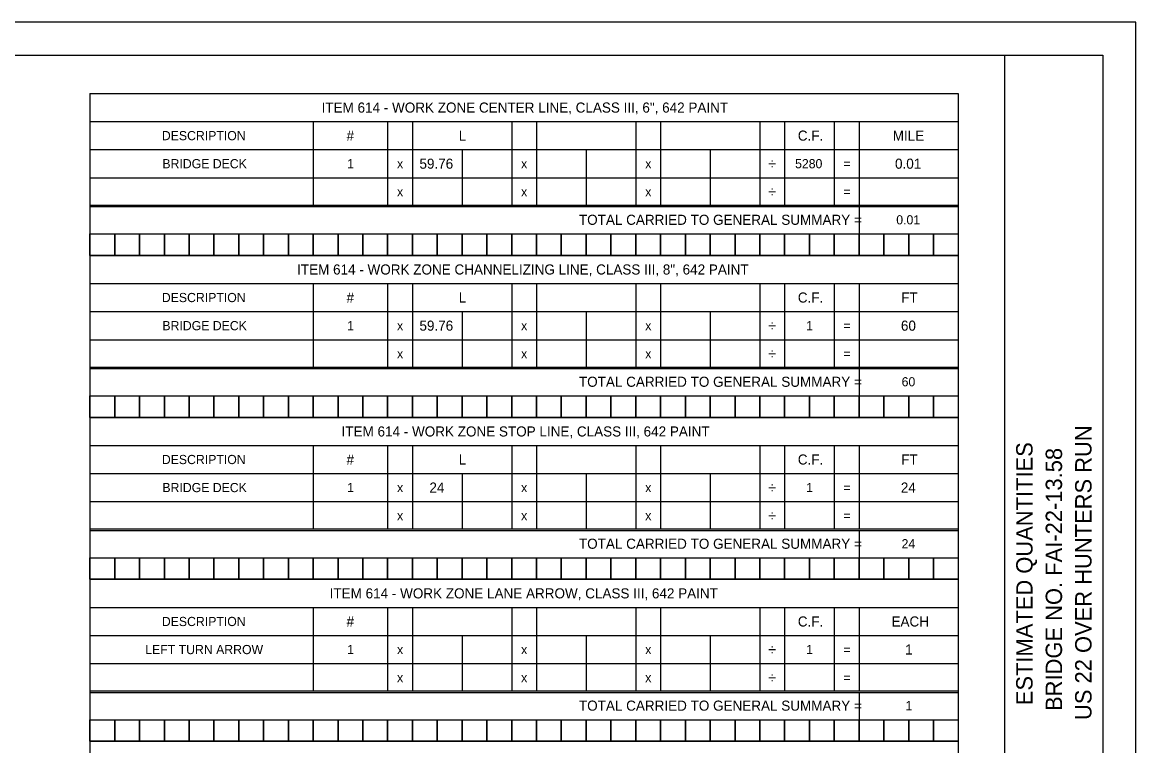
# Model space of a CAD drawing. Extents: x 0 to 34, y 0 to 22.
# Drawn here: x 17 to 34, y 10.96 to 22 of the extents above; entities that cross this region are included whole.
import ezdxf

# ---------------------------------------------------------------- set-up
doc = ezdxf.new("R2010")
doc.units = 0
for name, color, linetype in [('SH_Border', 7, 'Continuous'), ('SH_Cut_Line', 7, 'Continuous'), ('SH_Data', 7, 'Continuous'), ('SH_Text', 7, 'Continuous')]:
    doc.layers.add(name, color=color, linetype=linetype)

msp = doc.modelspace()

# ---------------------------------------------------------------- linework, layer by layer
at = {"layer": 'SH_Border'}
msp.add_line((32, 0.5), (32, 21.5), dxfattribs=at)
msp.add_lwpolyline([(1.5, 21.5), (33.5, 21.5), (33.5, 0.5), (1.5, 0.5)], close=True, dxfattribs=at)
at = {"layer": 'SH_Cut_Line'}
msp.add_lwpolyline([(0, 0), (34, 0), (34, 22), (0, 22)], close=True, dxfattribs=at)
at = {"layer": 'SH_Text'}
for p, q in [((18.032, 20.914), (31.291, 20.914)), ((18.032, 20.914), (18.032, 19.19)), ((31.291, 20.914), (31.291, 19.19)), ((18.032, 20.485), (31.291, 20.485)), ((21.442, 20.485), (21.442, 19.212)), ((22.578, 20.485), (22.578, 19.212)), ((22.957, 20.485), (22.957, 19.212)), ((24.472, 20.485), (24.472, 19.212)), ((24.851, 20.485), (24.851, 19.212)), ((26.367, 20.485), (26.367, 19.212)), ((26.745, 20.485), (26.745, 19.212)), ((28.261, 20.485), (28.261, 19.212)), ((28.639, 20.485), (28.639, 19.212)), ((29.397, 20.485), (29.397, 19.212)), ((29.776, 20.485), (29.776, 19.212)), ((18.032, 20.057), (31.291, 20.057)), ((23.715, 20.057), (23.715, 19.212)), ((25.609, 20.057), (25.609, 19.212)), ((27.503, 20.057), (27.503, 19.212)), ((18.032, 19.629), (31.291, 19.629)), ((18.032, 19.212), (31.291, 19.212)), ((18.032, 19.212), (18.032, 16.719)), ((31.291, 19.212), (31.291, 16.719)), ((18.032, 19.19), (31.291, 19.19)), ((29.776, 19.19), (29.776, 18.772)), ((18.032, 18.772), (31.291, 18.772)), ((18.032, 18.443), (31.291, 18.443)), ((18.032, 18.015), (31.291, 18.015)), ((21.442, 18.015), (21.442, 16.741)), ((22.578, 18.015), (22.578, 16.741)), ((22.957, 18.015), (22.957, 16.741)), ((24.472, 18.015), (24.472, 16.741)), ((24.851, 18.015), (24.851, 16.741)), ((26.367, 18.015), (26.367, 16.741)), ((26.745, 18.015), (26.745, 16.741)), ((28.261, 18.015), (28.261, 16.741)), ((28.639, 18.015), (28.639, 16.741)), ((29.397, 18.015), (29.397, 16.741)), ((29.776, 18.015), (29.776, 16.741)), ((18.032, 17.587), (31.291, 17.587)), ((23.715, 17.587), (23.715, 16.741)), ((25.609, 17.587), (25.609, 16.741)), ((27.503, 17.587), (27.503, 16.741)), ((18.032, 17.158), (31.291, 17.158)), ((18.032, 16.741), (31.291, 16.741)), ((18.032, 16.741), (18.032, 14.248)), ((18.032, 16.719), (31.291, 16.719)), ((29.776, 16.719), (29.776, 16.302)), ((31.291, 16.741), (31.291, 14.248)), ((18.032, 16.302), (31.291, 16.302)), ((18.032, 15.972), (31.291, 15.972)), ((18.032, 15.544), (31.291, 15.544)), ((21.442, 15.544), (21.442, 14.27)), ((22.578, 15.544), (22.578, 14.27)), ((22.957, 15.544), (22.957, 14.27)), ((24.472, 15.544), (24.472, 14.27)), ((24.851, 15.544), (24.851, 14.27)), ((26.367, 15.544), (26.367, 14.27)), ((26.745, 15.544), (26.745, 14.27)), ((28.261, 15.544), (28.261, 14.27)), ((28.639, 15.544), (28.639, 14.27)), ((29.397, 15.544), (29.397, 14.27)), ((29.776, 15.544), (29.776, 14.27)), ((18.032, 15.116), (31.291, 15.116)), ((23.715, 15.116), (23.715, 14.27)), ((25.609, 15.116), (25.609, 14.27)), ((27.503, 15.116), (27.503, 14.27)), ((18.032, 14.688), (31.291, 14.688)), ((18.032, 14.27), (31.291, 14.27)), ((18.032, 14.27), (18.032, 11.778)), ((18.032, 14.248), (31.291, 14.248)), ((29.776, 14.248), (29.776, 13.831)), ((31.291, 14.27), (31.291, 11.778)), ((18.032, 13.831), (31.291, 13.831)), ((18.032, 13.502), (31.291, 13.502)), ((18.032, 13.074), (31.291, 13.074)), ((21.442, 13.074), (21.442, 11.8)), ((22.578, 13.074), (22.578, 11.8)), ((22.957, 13.074), (22.957, 11.8)), ((24.472, 13.074), (24.472, 11.8)), ((24.851, 13.074), (24.851, 11.8)), ((26.367, 13.074), (26.367, 11.8)), ((26.745, 13.074), (26.745, 11.8)), ((28.261, 13.074), (28.261, 11.8)), ((28.639, 13.074), (28.639, 11.8)), ((29.397, 13.074), (29.397, 11.8)), ((29.776, 13.074), (29.776, 11.8)), ((18.032, 12.645), (31.291, 12.645)), ((23.715, 12.645), (23.715, 11.8)), ((25.609, 12.645), (25.609, 11.8)), ((27.503, 12.645), (27.503, 11.8)), ((18.032, 12.217), (31.291, 12.217)), ((18.032, 11.8), (31.291, 11.8)), ((18.032, 11.8), (18.032, 8.879)), ((18.032, 11.778), (31.291, 11.778)), ((29.776, 11.778), (29.776, 11.361)), ((31.291, 11.8), (31.291, 8.879)), ((18.032, 11.361), (31.291, 11.361)), ((18.032, 11.031), (31.291, 11.031))]:
    msp.add_line(p, q, dxfattribs=at)
for points in [[(18.032, 18.772), (18.411, 18.772), (18.411, 18.443), (18.032, 18.443)], [(18.411, 18.772), (18.79, 18.772), (18.79, 18.443), (18.411, 18.443)], [(18.79, 18.772), (19.169, 18.772), (19.169, 18.443), (18.79, 18.443)], [(19.169, 18.772), (19.548, 18.772), (19.548, 18.443), (19.169, 18.443)], [(19.548, 18.772), (19.927, 18.772), (19.927, 18.443), (19.548, 18.443)], [(19.927, 18.772), (20.305, 18.772), (20.305, 18.443), (19.927, 18.443)], [(20.305, 18.772), (20.684, 18.772), (20.684, 18.443), (20.305, 18.443)], [(20.684, 18.772), (21.063, 18.772), (21.063, 18.443), (20.684, 18.443)], [(21.063, 18.772), (21.442, 18.772), (21.442, 18.443), (21.063, 18.443)], [(21.442, 18.772), (21.821, 18.772), (21.821, 18.443), (21.442, 18.443)], [(21.821, 18.772), (22.199, 18.772), (22.199, 18.443), (21.821, 18.443)], [(22.199, 18.772), (22.578, 18.772), (22.578, 18.443), (22.199, 18.443)], [(22.578, 18.772), (22.957, 18.772), (22.957, 18.443), (22.578, 18.443)], [(22.957, 18.772), (23.336, 18.772), (23.336, 18.443), (22.957, 18.443)], [(23.336, 18.772), (23.715, 18.772), (23.715, 18.443), (23.336, 18.443)], [(23.715, 18.772), (24.094, 18.772), (24.094, 18.443), (23.715, 18.443)], [(24.094, 18.772), (24.472, 18.772), (24.472, 18.443), (24.094, 18.443)], [(24.472, 18.772), (24.851, 18.772), (24.851, 18.443), (24.472, 18.443)], [(24.851, 18.772), (25.23, 18.772), (25.23, 18.443), (24.851, 18.443)], [(25.23, 18.772), (25.609, 18.772), (25.609, 18.443), (25.23, 18.443)], [(25.609, 18.772), (25.988, 18.772), (25.988, 18.443), (25.609, 18.443)], [(25.988, 18.772), (26.367, 18.772), (26.367, 18.443), (25.988, 18.443)], [(26.367, 18.772), (26.745, 18.772), (26.745, 18.443), (26.367, 18.443)], [(26.745, 18.772), (27.124, 18.772), (27.124, 18.443), (26.745, 18.443)], [(27.124, 18.772), (27.503, 18.772), (27.503, 18.443), (27.124, 18.443)], [(27.503, 18.772), (27.882, 18.772), (27.882, 18.443), (27.503, 18.443)], [(27.882, 18.772), (28.261, 18.772), (28.261, 18.443), (27.882, 18.443)], [(28.261, 18.772), (28.639, 18.772), (28.639, 18.443), (28.261, 18.443)], [(28.639, 18.772), (29.018, 18.772), (29.018, 18.443), (28.639, 18.443)], [(29.018, 18.772), (29.397, 18.772), (29.397, 18.443), (29.018, 18.443)], [(29.397, 18.772), (29.776, 18.772), (29.776, 18.443), (29.397, 18.443)], [(29.776, 18.772), (30.155, 18.772), (30.155, 18.443), (29.776, 18.443)], [(30.155, 18.772), (30.534, 18.772), (30.534, 18.443), (30.155, 18.443)], [(30.534, 18.772), (30.912, 18.772), (30.912, 18.443), (30.534, 18.443)], [(30.912, 18.772), (31.291, 18.772), (31.291, 18.443), (30.912, 18.443)], [(18.032, 16.302), (18.411, 16.302), (18.411, 15.972), (18.032, 15.972)], [(18.411, 16.302), (18.79, 16.302), (18.79, 15.972), (18.411, 15.972)], [(18.79, 16.302), (19.169, 16.302), (19.169, 15.972), (18.79, 15.972)], [(19.169, 16.302), (19.548, 16.302), (19.548, 15.972), (19.169, 15.972)], [(19.548, 16.302), (19.927, 16.302), (19.927, 15.972), (19.548, 15.972)], [(19.927, 16.302), (20.305, 16.302), (20.305, 15.972), (19.927, 15.972)], [(20.305, 16.302), (20.684, 16.302), (20.684, 15.972), (20.305, 15.972)], [(20.684, 16.302), (21.063, 16.302), (21.063, 15.972), (20.684, 15.972)], [(21.063, 16.302), (21.442, 16.302), (21.442, 15.972), (21.063, 15.972)], [(21.442, 16.302), (21.821, 16.302), (21.821, 15.972), (21.442, 15.972)], [(21.821, 16.302), (22.199, 16.302), (22.199, 15.972), (21.821, 15.972)], [(22.199, 16.302), (22.578, 16.302), (22.578, 15.972), (22.199, 15.972)], [(22.578, 16.302), (22.957, 16.302), (22.957, 15.972), (22.578, 15.972)], [(22.957, 16.302), (23.336, 16.302), (23.336, 15.972), (22.957, 15.972)], [(23.336, 16.302), (23.715, 16.302), (23.715, 15.972), (23.336, 15.972)], [(23.715, 16.302), (24.094, 16.302), (24.094, 15.972), (23.715, 15.972)], [(24.094, 16.302), (24.472, 16.302), (24.472, 15.972), (24.094, 15.972)], [(24.472, 16.302), (24.851, 16.302), (24.851, 15.972), (24.472, 15.972)], [(24.851, 16.302), (25.23, 16.302), (25.23, 15.972), (24.851, 15.972)], [(25.23, 16.302), (25.609, 16.302), (25.609, 15.972), (25.23, 15.972)], [(25.609, 16.302), (25.988, 16.302), (25.988, 15.972), (25.609, 15.972)], [(25.988, 16.302), (26.367, 16.302), (26.367, 15.972), (25.988, 15.972)], [(26.367, 16.302), (26.745, 16.302), (26.745, 15.972), (26.367, 15.972)], [(26.745, 16.302), (27.124, 16.302), (27.124, 15.972), (26.745, 15.972)], [(27.124, 16.302), (27.503, 16.302), (27.503, 15.972), (27.124, 15.972)], [(27.503, 16.302), (27.882, 16.302), (27.882, 15.972), (27.503, 15.972)], [(27.882, 16.302), (28.261, 16.302), (28.261, 15.972), (27.882, 15.972)], [(28.261, 16.302), (28.639, 16.302), (28.639, 15.972), (28.261, 15.972)], [(28.639, 16.302), (29.018, 16.302), (29.018, 15.972), (28.639, 15.972)], [(29.018, 16.302), (29.397, 16.302), (29.397, 15.972), (29.018, 15.972)], [(29.397, 16.302), (29.776, 16.302), (29.776, 15.972), (29.397, 15.972)], [(29.776, 16.302), (30.155, 16.302), (30.155, 15.972), (29.776, 15.972)], [(30.155, 16.302), (30.534, 16.302), (30.534, 15.972), (30.155, 15.972)], [(30.534, 16.302), (30.912, 16.302), (30.912, 15.972), (30.534, 15.972)], [(30.912, 16.302), (31.291, 16.302), (31.291, 15.972), (30.912, 15.972)], [(18.032, 13.831), (18.411, 13.831), (18.411, 13.502), (18.032, 13.502)], [(18.411, 13.831), (18.79, 13.831), (18.79, 13.502), (18.411, 13.502)], [(18.79, 13.831), (19.169, 13.831), (19.169, 13.502), (18.79, 13.502)], [(19.169, 13.831), (19.548, 13.831), (19.548, 13.502), (19.169, 13.502)], [(19.548, 13.831), (19.927, 13.831), (19.927, 13.502), (19.548, 13.502)], [(19.927, 13.831), (20.305, 13.831), (20.305, 13.502), (19.927, 13.502)], [(20.305, 13.831), (20.684, 13.831), (20.684, 13.502), (20.305, 13.502)], [(20.684, 13.831), (21.063, 13.831), (21.063, 13.502), (20.684, 13.502)], [(21.063, 13.831), (21.442, 13.831), (21.442, 13.502), (21.063, 13.502)], [(21.442, 13.831), (21.821, 13.831), (21.821, 13.502), (21.442, 13.502)], [(21.821, 13.831), (22.199, 13.831), (22.199, 13.502), (21.821, 13.502)], [(22.199, 13.831), (22.578, 13.831), (22.578, 13.502), (22.199, 13.502)], [(22.578, 13.831), (22.957, 13.831), (22.957, 13.502), (22.578, 13.502)], [(22.957, 13.831), (23.336, 13.831), (23.336, 13.502), (22.957, 13.502)], [(23.336, 13.831), (23.715, 13.831), (23.715, 13.502), (23.336, 13.502)], [(23.715, 13.831), (24.094, 13.831), (24.094, 13.502), (23.715, 13.502)], [(24.094, 13.831), (24.472, 13.831), (24.472, 13.502), (24.094, 13.502)], [(24.472, 13.831), (24.851, 13.831), (24.851, 13.502), (24.472, 13.502)], [(24.851, 13.831), (25.23, 13.831), (25.23, 13.502), (24.851, 13.502)], [(25.23, 13.831), (25.609, 13.831), (25.609, 13.502), (25.23, 13.502)], [(25.609, 13.831), (25.988, 13.831), (25.988, 13.502), (25.609, 13.502)], [(25.988, 13.831), (26.367, 13.831), (26.367, 13.502), (25.988, 13.502)], [(26.367, 13.831), (26.745, 13.831), (26.745, 13.502), (26.367, 13.502)], [(26.745, 13.831), (27.124, 13.831), (27.124, 13.502), (26.745, 13.502)], [(27.124, 13.831), (27.503, 13.831), (27.503, 13.502), (27.124, 13.502)], [(27.503, 13.831), (27.882, 13.831), (27.882, 13.502), (27.503, 13.502)], [(27.882, 13.831), (28.261, 13.831), (28.261, 13.502), (27.882, 13.502)], [(28.261, 13.831), (28.639, 13.831), (28.639, 13.502), (28.261, 13.502)], [(28.639, 13.831), (29.018, 13.831), (29.018, 13.502), (28.639, 13.502)], [(29.018, 13.831), (29.397, 13.831), (29.397, 13.502), (29.018, 13.502)], [(29.397, 13.831), (29.776, 13.831), (29.776, 13.502), (29.397, 13.502)], [(29.776, 13.831), (30.155, 13.831), (30.155, 13.502), (29.776, 13.502)], [(30.155, 13.831), (30.534, 13.831), (30.534, 13.502), (30.155, 13.502)], [(30.534, 13.831), (30.912, 13.831), (30.912, 13.502), (30.534, 13.502)], [(30.912, 13.831), (31.291, 13.831), (31.291, 13.502), (30.912, 13.502)], [(18.032, 11.361), (18.411, 11.361), (18.411, 11.031), (18.032, 11.031)], [(18.411, 11.361), (18.79, 11.361), (18.79, 11.031), (18.411, 11.031)], [(18.79, 11.361), (19.169, 11.361), (19.169, 11.031), (18.79, 11.031)], [(19.169, 11.361), (19.548, 11.361), (19.548, 11.031), (19.169, 11.031)], [(19.548, 11.361), (19.927, 11.361), (19.927, 11.031), (19.548, 11.031)], [(19.927, 11.361), (20.305, 11.361), (20.305, 11.031), (19.927, 11.031)], [(20.305, 11.361), (20.684, 11.361), (20.684, 11.031), (20.305, 11.031)], [(20.684, 11.361), (21.063, 11.361), (21.063, 11.031), (20.684, 11.031)], [(21.063, 11.361), (21.442, 11.361), (21.442, 11.031), (21.063, 11.031)], [(21.442, 11.361), (21.821, 11.361), (21.821, 11.031), (21.442, 11.031)], [(21.821, 11.361), (22.199, 11.361), (22.199, 11.031), (21.821, 11.031)], [(22.199, 11.361), (22.578, 11.361), (22.578, 11.031), (22.199, 11.031)], [(22.578, 11.361), (22.957, 11.361), (22.957, 11.031), (22.578, 11.031)], [(22.957, 11.361), (23.336, 11.361), (23.336, 11.031), (22.957, 11.031)], [(23.336, 11.361), (23.715, 11.361), (23.715, 11.031), (23.336, 11.031)], [(23.715, 11.361), (24.094, 11.361), (24.094, 11.031), (23.715, 11.031)], [(24.094, 11.361), (24.472, 11.361), (24.472, 11.031), (24.094, 11.031)], [(24.472, 11.361), (24.851, 11.361), (24.851, 11.031), (24.472, 11.031)], [(24.851, 11.361), (25.23, 11.361), (25.23, 11.031), (24.851, 11.031)], [(25.23, 11.361), (25.609, 11.361), (25.609, 11.031), (25.23, 11.031)], [(25.609, 11.361), (25.988, 11.361), (25.988, 11.031), (25.609, 11.031)], [(25.988, 11.361), (26.367, 11.361), (26.367, 11.031), (25.988, 11.031)], [(26.367, 11.361), (26.745, 11.361), (26.745, 11.031), (26.367, 11.031)], [(26.745, 11.361), (27.124, 11.361), (27.124, 11.031), (26.745, 11.031)], [(27.124, 11.361), (27.503, 11.361), (27.503, 11.031), (27.124, 11.031)], [(27.503, 11.361), (27.882, 11.361), (27.882, 11.031), (27.503, 11.031)], [(27.882, 11.361), (28.261, 11.361), (28.261, 11.031), (27.882, 11.031)], [(28.261, 11.361), (28.639, 11.361), (28.639, 11.031), (28.261, 11.031)], [(28.639, 11.361), (29.018, 11.361), (29.018, 11.031), (28.639, 11.031)], [(29.018, 11.361), (29.397, 11.361), (29.397, 11.031), (29.018, 11.031)], [(29.397, 11.361), (29.776, 11.361), (29.776, 11.031), (29.397, 11.031)], [(29.776, 11.361), (30.155, 11.361), (30.155, 11.031), (29.776, 11.031)], [(30.155, 11.361), (30.534, 11.361), (30.534, 11.031), (30.155, 11.031)], [(30.534, 11.361), (30.912, 11.361), (30.912, 11.031), (30.534, 11.031)], [(30.912, 11.361), (31.291, 11.361), (31.291, 11.031), (30.912, 11.031)]]:
    msp.add_lwpolyline(points, close=True, dxfattribs=at)

# ---------------------------------------------------------------- texts
at = {"layer": 'SH_Data'}
for s, p in [('US 22 OVER HUNTERS RUN', (33.325, 11.356)), ('ESTIMATED QUANTITIES', (32.425, 11.582)), ('BRIDGE NO. FAI-22-13.58', (32.875, 11.494))]:
    msp.add_text(s, height=0.25, rotation=90, dxfattribs=at).set_placement(p)
at = {"layer": 'SH_Text'}
for s, height, p in [('ITEM 614 - WORK ZONE CENTER LINE, CLASS III, 6", 642 PAINT', 0.154, (21.57, 20.622)), ('DESCRIPTION', 0.14, (19.131, 20.201)), ('#', 0.154, (21.951, 20.194)), ('L', 0.154, (23.664, 20.194)), ('C.F.', 0.154, (28.841, 20.194)), ('MILE', 0.154, (30.29, 20.194)), ('BRIDGE DECK', 0.14, (19.139, 19.773)), ('1', 0.14, (21.96, 19.773)), ('59.76', 0.154, (23.064, 19.766)), ('÷', 0.168, (28.388, 19.759)), ('5280', 0.14, (28.799, 19.773)), ('0.01', 0.154, (30.325, 19.766)), ('x', 0.14, (22.722, 19.773)), ('x', 0.14, (24.616, 19.773)), ('x', 0.14, (26.511, 19.773)), ('=', 0.14, (29.537, 19.773)), ('x', 0.14, (22.722, 19.345)), ('x', 0.14, (24.616, 19.345)), ('x', 0.14, (26.511, 19.345)), ('÷', 0.168, (28.388, 19.331)), ('=', 0.14, (29.537, 19.345)), ('TOTAL CARRIED TO GENERAL SUMMARY =', 0.154, (25.499, 18.91)), ('0.01', 0.14, (30.344, 18.917)), ('ITEM 614 - WORK ZONE CHANNELIZING LINE, CLASS III, 8", 642 PAINT', 0.154, (21.196, 18.152)), ('DESCRIPTION', 0.14, (19.131, 17.731)), ('#', 0.154, (21.951, 17.724)), ('L', 0.154, (23.664, 17.724)), ('C.F.', 0.154, (28.841, 17.724)), ('FT', 0.154, (30.419, 17.724)), ('BRIDGE DECK', 0.14, (19.139, 17.302)), ('1', 0.14, (21.96, 17.302)), ('x', 0.14, (22.722, 17.302)), ('59.76', 0.154, (23.064, 17.295)), ('x', 0.14, (24.616, 17.302)), ('x', 0.14, (26.511, 17.302)), ('÷', 0.168, (28.388, 17.288)), ('1', 0.14, (28.968, 17.302)), ('=', 0.14, (29.537, 17.302)), ('60', 0.154, (30.415, 17.295)), ('x', 0.14, (22.722, 16.874)), ('x', 0.14, (24.616, 16.874)), ('x', 0.14, (26.511, 16.874)), ('÷', 0.168, (28.388, 16.86)), ('=', 0.14, (29.537, 16.874)), ('TOTAL CARRIED TO GENERAL SUMMARY =', 0.154, (25.499, 16.439)), ('60', 0.14, (30.426, 16.446)), ('ITEM 614 - WORK ZONE STOP LINE, CLASS III, 642 PAINT', 0.154, (21.875, 15.681)), ('DESCRIPTION', 0.14, (19.131, 15.26)), ('#', 0.154, (21.951, 15.253)), ('L', 0.154, (23.664, 15.253)), ('C.F.', 0.154, (28.841, 15.253)), ('FT', 0.154, (30.419, 15.253)), ('BRIDGE DECK', 0.14, (19.139, 14.832)), ('1', 0.14, (21.96, 14.832)), ('24', 0.154, (23.216, 14.825)), ('1', 0.14, (28.968, 14.832)), ('24', 0.154, (30.414, 14.825)), ('x', 0.14, (22.722, 14.832)), ('x', 0.14, (24.616, 14.832)), ('x', 0.14, (26.511, 14.832)), ('÷', 0.168, (28.388, 14.818)), ('=', 0.14, (29.537, 14.832)), ('x', 0.14, (22.722, 14.404)), ('x', 0.14, (24.616, 14.404)), ('x', 0.14, (26.511, 14.404)), ('÷', 0.168, (28.388, 14.39)), ('=', 0.14, (29.537, 14.404)), ('TOTAL CARRIED TO GENERAL SUMMARY =', 0.154, (25.499, 13.968)), ('24', 0.14, (30.425, 13.975)), ('ITEM 614 - WORK ZONE LANE ARROW, CLASS III, 642 PAINT', 0.154, (21.693, 13.211)), ('DESCRIPTION', 0.14, (19.131, 12.789)), ('#', 0.154, (21.951, 12.782)), ('C.F.', 0.154, (28.841, 12.782)), ('EACH', 0.154, (30.271, 12.782)), ('LEFT TURN ARROW', 0.14, (18.878, 12.361)), ('1', 0.14, (21.96, 12.361)), ('x', 0.14, (22.722, 12.361)), ('x', 0.14, (24.616, 12.361)), ('x', 0.14, (26.511, 12.361)), ('÷', 0.168, (28.388, 12.347)), ('1', 0.14, (28.968, 12.361)), ('=', 0.14, (29.537, 12.361)), ('1', 0.154, (30.479, 12.354)), ('x', 0.14, (22.722, 11.933)), ('x', 0.14, (24.616, 11.933)), ('x', 0.14, (26.511, 11.933)), ('÷', 0.168, (28.388, 11.919)), ('=', 0.14, (29.537, 11.933)), ('TOTAL CARRIED TO GENERAL SUMMARY =', 0.154, (25.499, 11.498)), ('1', 0.14, (30.484, 11.505))]:
    msp.add_text(s, height=height, dxfattribs=at).set_placement(p)

doc.saveas('drawing.dxf')
